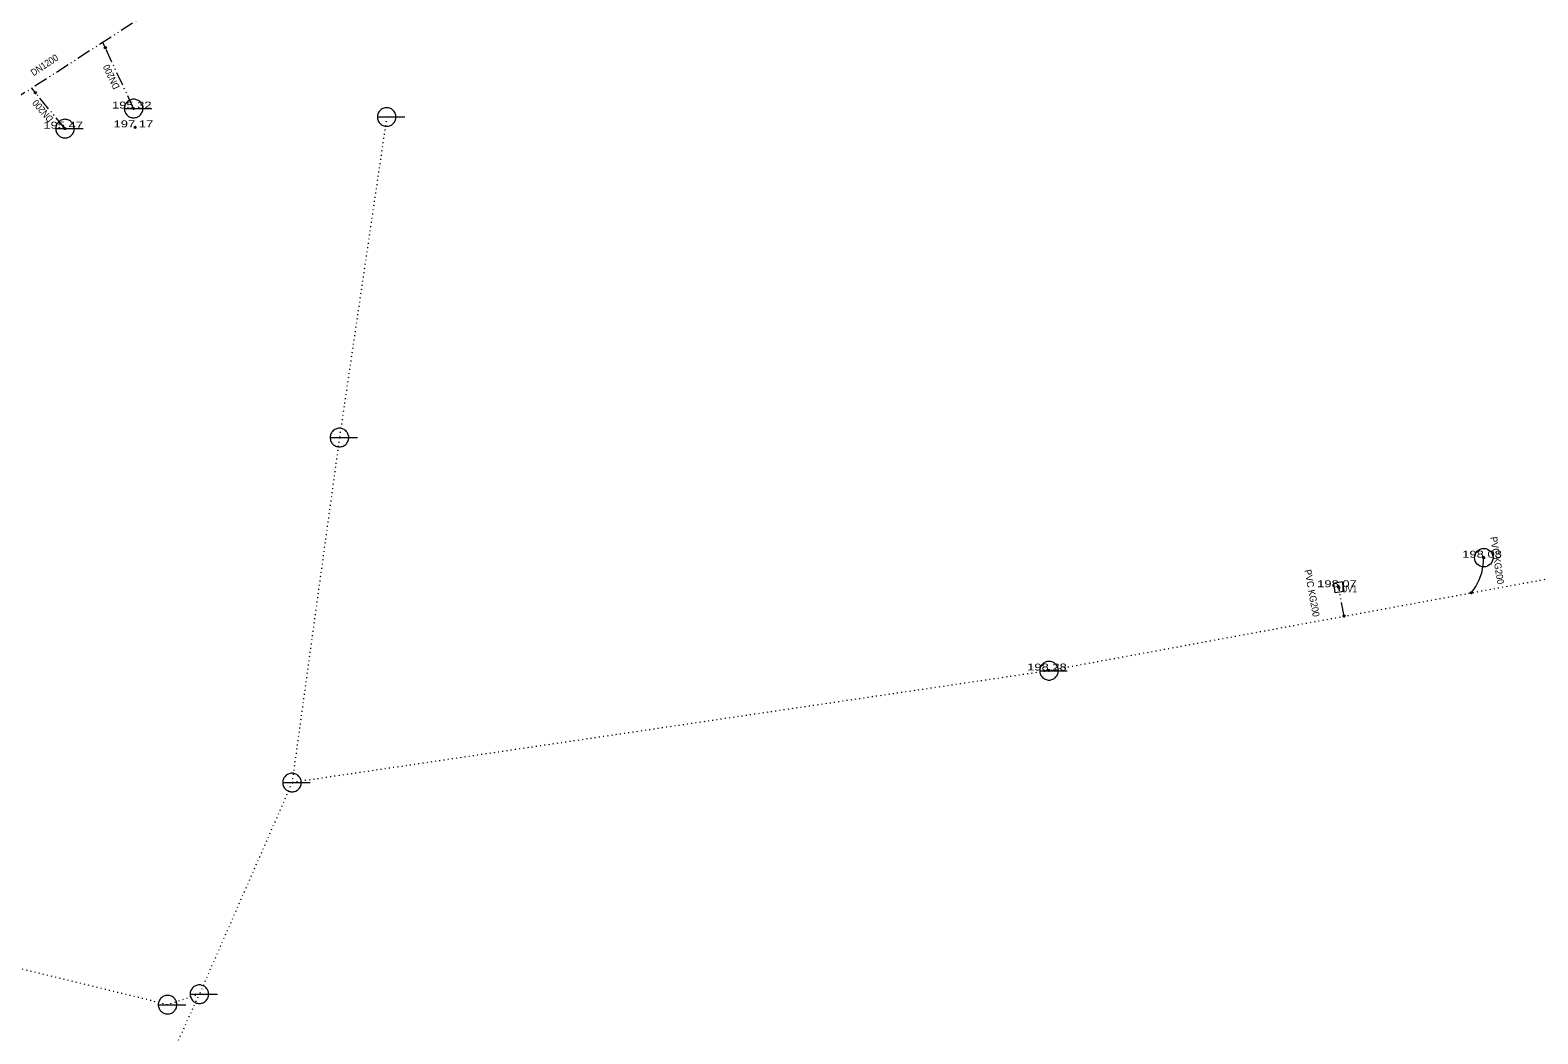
# Model space of a CAD drawing. Extents: x -688177 to -687620, y -1056713 to -1056287.
# Drawn here: x -687948.5 to -687785.1, y -1056606.6 to -1056497.8 of the extents above; entities that cross this region are included whole.
import ezdxf
from ezdxf.enums import TextEntityAlignment as Align

# ---------------------------------------------------------------- set-up
doc = ezdxf.new("R2010")
doc.units = 0
doc.header["$LTSCALE"] = 0.3
doc.header["$PDMODE"] = 32
doc.header["$PDSIZE"] = 0.15
for name, pattern in [('DASH_DOUBLE_DOT', [9.2, 5, -1.2, 0.3, -1.2, 0.3, -1.2]), ('DOTTED', [1.5, 0.3, -1.2]), ('LONG_DASHED', [7.5, 6, -1.5])]:
    doc.linetypes.add(name, pattern=pattern)
for name, color, linetype in [('1', 7, 'Continuous'), ('18', 7, 'Continuous'), ('19', 7, 'Continuous'), ('3', 7, 'Continuous')]:
    doc.layers.add(name, color=color, linetype=linetype)
for name, color, linetype, lineweight in [('10', 7, 'Continuous', 13), ('12', 7, 'Continuous', 13), ('46', 7, 'DOTTED', 13), ('50', 7, 'LONG_DASHED', 13), ('51', 7, 'DASH_DOUBLE_DOT', 13)]:
    doc.layers.add(name, color=color, linetype=linetype, lineweight=lineweight)

msp = doc.modelspace()

# ---------------------------------------------------------------- linework, layer by layer
at = {"layer": '1'}
for p in [(-687940.32, -1056499.71), (-687947.88, -1056504.6), (-687937.24, -1056506.31), (-687944.68, -1056508.49), (-687937.07, -1056508.35), (-687790.91, -1056555), (-687806.63, -1056558.2), (-687792.25, -1056558.81), (-687806.05, -1056561.34), (-687838.06, -1056567.23)]:
    msp.add_point(p, dxfattribs=at)
at = {"layer": '10'}
msp.add_line((-687806.669, -1056557.953), (-687806.591, -1056558.447), dxfattribs=at)
msp.add_lwpolyline([(-687807.202, -1056557.784), (-687807.046, -1056558.772), (-687806.058, -1056558.616), (-687806.214, -1056557.628)], close=True, dxfattribs=at)
msp.add_circle((-687790.91, -1056555), 1, dxfattribs=at)
at = {"layer": '12'}
for p, q in [((-687938.248, -1056506.31), (-687935.272, -1056506.31)), ((-687910.818, -1056507.23), (-687907.842, -1056507.23)), ((-687945.688, -1056508.49), (-687942.712, -1056508.49)), ((-687915.938, -1056541.98), (-687912.962, -1056541.98)), ((-687839.038, -1056567.26), (-687836.062, -1056567.26)), ((-687921.078, -1056579.38), (-687918.102, -1056579.38)), ((-687931.118, -1056602.32), (-687928.142, -1056602.32)), ((-687934.568, -1056603.46), (-687931.592, -1056603.46))]:
    msp.add_line(p, q, dxfattribs=at)
for points in [[(-687937.24, -1056505.302), (-687937.345, -1056505.308), (-687937.449, -1056505.324), (-687937.551, -1056505.352), (-687937.65, -1056505.39), (-687937.744, -1056505.437), (-687937.832, -1056505.495), (-687937.914, -1056505.561), (-687937.989, -1056505.636), (-687938.055, -1056505.718), (-687938.113, -1056505.806), (-687938.16, -1056505.9), (-687938.198, -1056505.999), (-687938.226, -1056506.101), (-687938.242, -1056506.205), (-687938.248, -1056506.31), (-687938.242, -1056506.415), (-687938.226, -1056506.52), (-687938.198, -1056506.622), (-687938.16, -1056506.72), (-687938.113, -1056506.814), (-687938.055, -1056506.903), (-687937.989, -1056506.985), (-687937.914, -1056507.059), (-687937.832, -1056507.125), (-687937.744, -1056507.183), (-687937.65, -1056507.231), (-687937.551, -1056507.269), (-687937.449, -1056507.296), (-687937.345, -1056507.312), (-687937.24, -1056507.318), (-687937.135, -1056507.312), (-687937.03, -1056507.296), (-687936.928, -1056507.269), (-687936.83, -1056507.231), (-687936.736, -1056507.183), (-687936.647, -1056507.125), (-687936.565, -1056507.059), (-687936.491, -1056506.985), (-687936.425, -1056506.903), (-687936.367, -1056506.814), (-687936.319, -1056506.72), (-687936.281, -1056506.622), (-687936.254, -1056506.52), (-687936.238, -1056506.415), (-687936.232, -1056506.31), (-687936.238, -1056506.205), (-687936.254, -1056506.101), (-687936.281, -1056505.999), (-687936.319, -1056505.9), (-687936.367, -1056505.806), (-687936.425, -1056505.718), (-687936.491, -1056505.636), (-687936.565, -1056505.561), (-687936.647, -1056505.495), (-687936.736, -1056505.437), (-687936.83, -1056505.39), (-687936.928, -1056505.352), (-687937.03, -1056505.324), (-687937.135, -1056505.308)], [(-687909.81, -1056506.222), (-687909.915, -1056506.228), (-687910.019, -1056506.244), (-687910.121, -1056506.272), (-687910.22, -1056506.31), (-687910.314, -1056506.357), (-687910.402, -1056506.415), (-687910.484, -1056506.481), (-687910.559, -1056506.556), (-687910.625, -1056506.638), (-687910.683, -1056506.726), (-687910.73, -1056506.82), (-687910.768, -1056506.919), (-687910.796, -1056507.021), (-687910.812, -1056507.125), (-687910.818, -1056507.23), (-687910.812, -1056507.335), (-687910.796, -1056507.44), (-687910.768, -1056507.542), (-687910.73, -1056507.64), (-687910.683, -1056507.734), (-687910.625, -1056507.823), (-687910.559, -1056507.905), (-687910.484, -1056507.979), (-687910.402, -1056508.045), (-687910.314, -1056508.103), (-687910.22, -1056508.151), (-687910.121, -1056508.189), (-687910.019, -1056508.216), (-687909.915, -1056508.232), (-687909.81, -1056508.238), (-687909.705, -1056508.232), (-687909.6, -1056508.216), (-687909.498, -1056508.189), (-687909.4, -1056508.151), (-687909.306, -1056508.103), (-687909.217, -1056508.045), (-687909.135, -1056507.979), (-687909.061, -1056507.905), (-687908.995, -1056507.823), (-687908.937, -1056507.734), (-687908.889, -1056507.64), (-687908.851, -1056507.542), (-687908.824, -1056507.44), (-687908.808, -1056507.335), (-687908.802, -1056507.23), (-687908.808, -1056507.125), (-687908.824, -1056507.021), (-687908.851, -1056506.919), (-687908.889, -1056506.82), (-687908.937, -1056506.726), (-687908.995, -1056506.638), (-687909.061, -1056506.556), (-687909.135, -1056506.481), (-687909.217, -1056506.415), (-687909.306, -1056506.357), (-687909.4, -1056506.31), (-687909.498, -1056506.272), (-687909.6, -1056506.244), (-687909.705, -1056506.228)], [(-687944.68, -1056507.482), (-687944.785, -1056507.488), (-687944.889, -1056507.504), (-687944.991, -1056507.532), (-687945.09, -1056507.57), (-687945.184, -1056507.617), (-687945.272, -1056507.675), (-687945.354, -1056507.741), (-687945.429, -1056507.816), (-687945.495, -1056507.898), (-687945.553, -1056507.986), (-687945.6, -1056508.08), (-687945.638, -1056508.179), (-687945.666, -1056508.281), (-687945.682, -1056508.385), (-687945.688, -1056508.49), (-687945.682, -1056508.595), (-687945.666, -1056508.7), (-687945.638, -1056508.802), (-687945.6, -1056508.9), (-687945.553, -1056508.994), (-687945.495, -1056509.083), (-687945.429, -1056509.165), (-687945.354, -1056509.239), (-687945.272, -1056509.305), (-687945.184, -1056509.363), (-687945.09, -1056509.411), (-687944.991, -1056509.449), (-687944.889, -1056509.476), (-687944.785, -1056509.492), (-687944.68, -1056509.498), (-687944.575, -1056509.492), (-687944.47, -1056509.476), (-687944.368, -1056509.449), (-687944.27, -1056509.411), (-687944.176, -1056509.363), (-687944.087, -1056509.305), (-687944.005, -1056509.239), (-687943.931, -1056509.165), (-687943.865, -1056509.083), (-687943.807, -1056508.994), (-687943.759, -1056508.9), (-687943.721, -1056508.802), (-687943.694, -1056508.7), (-687943.678, -1056508.595), (-687943.672, -1056508.49), (-687943.678, -1056508.385), (-687943.694, -1056508.281), (-687943.721, -1056508.179), (-687943.759, -1056508.08), (-687943.807, -1056507.986), (-687943.865, -1056507.898), (-687943.931, -1056507.816), (-687944.005, -1056507.741), (-687944.087, -1056507.675), (-687944.176, -1056507.617), (-687944.27, -1056507.57), (-687944.368, -1056507.532), (-687944.47, -1056507.504), (-687944.575, -1056507.488)], [(-687914.93, -1056540.972), (-687915.035, -1056540.978), (-687915.139, -1056540.994), (-687915.241, -1056541.022), (-687915.34, -1056541.06), (-687915.434, -1056541.107), (-687915.522, -1056541.165), (-687915.604, -1056541.231), (-687915.679, -1056541.306), (-687915.745, -1056541.388), (-687915.803, -1056541.476), (-687915.85, -1056541.57), (-687915.888, -1056541.669), (-687915.916, -1056541.771), (-687915.932, -1056541.875), (-687915.938, -1056541.98), (-687915.932, -1056542.085), (-687915.916, -1056542.19), (-687915.888, -1056542.292), (-687915.85, -1056542.39), (-687915.803, -1056542.484), (-687915.745, -1056542.573), (-687915.679, -1056542.655), (-687915.604, -1056542.729), (-687915.522, -1056542.795), (-687915.434, -1056542.853), (-687915.34, -1056542.901), (-687915.241, -1056542.939), (-687915.139, -1056542.966), (-687915.035, -1056542.982), (-687914.93, -1056542.988), (-687914.825, -1056542.982), (-687914.72, -1056542.966), (-687914.618, -1056542.939), (-687914.52, -1056542.901), (-687914.426, -1056542.853), (-687914.337, -1056542.795), (-687914.255, -1056542.729), (-687914.181, -1056542.655), (-687914.115, -1056542.573), (-687914.057, -1056542.484), (-687914.009, -1056542.39), (-687913.971, -1056542.292), (-687913.944, -1056542.19), (-687913.928, -1056542.085), (-687913.922, -1056541.98), (-687913.928, -1056541.875), (-687913.944, -1056541.771), (-687913.971, -1056541.669), (-687914.009, -1056541.57), (-687914.057, -1056541.476), (-687914.115, -1056541.388), (-687914.181, -1056541.306), (-687914.255, -1056541.231), (-687914.337, -1056541.165), (-687914.426, -1056541.107), (-687914.52, -1056541.06), (-687914.618, -1056541.022), (-687914.72, -1056540.994), (-687914.825, -1056540.978)], [(-687838.03, -1056566.252), (-687838.135, -1056566.258), (-687838.239, -1056566.274), (-687838.341, -1056566.302), (-687838.44, -1056566.34), (-687838.534, -1056566.387), (-687838.622, -1056566.445), (-687838.704, -1056566.511), (-687838.779, -1056566.586), (-687838.845, -1056566.668), (-687838.903, -1056566.756), (-687838.95, -1056566.85), (-687838.988, -1056566.949), (-687839.016, -1056567.051), (-687839.032, -1056567.155), (-687839.038, -1056567.26), (-687839.032, -1056567.365), (-687839.016, -1056567.47), (-687838.988, -1056567.572), (-687838.95, -1056567.67), (-687838.903, -1056567.764), (-687838.845, -1056567.853), (-687838.779, -1056567.935), (-687838.704, -1056568.009), (-687838.622, -1056568.075), (-687838.534, -1056568.133), (-687838.44, -1056568.181), (-687838.341, -1056568.219), (-687838.239, -1056568.246), (-687838.135, -1056568.262), (-687838.03, -1056568.268), (-687837.925, -1056568.262), (-687837.82, -1056568.246), (-687837.718, -1056568.219), (-687837.62, -1056568.181), (-687837.526, -1056568.133), (-687837.437, -1056568.075), (-687837.355, -1056568.009), (-687837.281, -1056567.935), (-687837.215, -1056567.853), (-687837.157, -1056567.764), (-687837.109, -1056567.67), (-687837.071, -1056567.572), (-687837.044, -1056567.47), (-687837.028, -1056567.365), (-687837.022, -1056567.26), (-687837.028, -1056567.155), (-687837.044, -1056567.051), (-687837.071, -1056566.949), (-687837.109, -1056566.85), (-687837.157, -1056566.756), (-687837.215, -1056566.668), (-687837.281, -1056566.586), (-687837.355, -1056566.511), (-687837.437, -1056566.445), (-687837.526, -1056566.387), (-687837.62, -1056566.34), (-687837.718, -1056566.302), (-687837.82, -1056566.274), (-687837.925, -1056566.258)], [(-687920.07, -1056578.372), (-687920.175, -1056578.378), (-687920.279, -1056578.394), (-687920.381, -1056578.422), (-687920.48, -1056578.46), (-687920.574, -1056578.507), (-687920.662, -1056578.565), (-687920.744, -1056578.631), (-687920.819, -1056578.706), (-687920.885, -1056578.788), (-687920.943, -1056578.876), (-687920.99, -1056578.97), (-687921.028, -1056579.069), (-687921.056, -1056579.171), (-687921.072, -1056579.275), (-687921.078, -1056579.38), (-687921.072, -1056579.485), (-687921.056, -1056579.59), (-687921.028, -1056579.692), (-687920.99, -1056579.79), (-687920.943, -1056579.884), (-687920.885, -1056579.973), (-687920.819, -1056580.055), (-687920.744, -1056580.129), (-687920.662, -1056580.195), (-687920.574, -1056580.253), (-687920.48, -1056580.301), (-687920.381, -1056580.339), (-687920.279, -1056580.366), (-687920.175, -1056580.382), (-687920.07, -1056580.388), (-687919.965, -1056580.382), (-687919.86, -1056580.366), (-687919.758, -1056580.339), (-687919.66, -1056580.301), (-687919.566, -1056580.253), (-687919.477, -1056580.195), (-687919.395, -1056580.129), (-687919.321, -1056580.055), (-687919.255, -1056579.973), (-687919.197, -1056579.884), (-687919.149, -1056579.79), (-687919.111, -1056579.692), (-687919.084, -1056579.59), (-687919.068, -1056579.485), (-687919.062, -1056579.38), (-687919.068, -1056579.275), (-687919.084, -1056579.171), (-687919.111, -1056579.069), (-687919.149, -1056578.97), (-687919.197, -1056578.876), (-687919.255, -1056578.788), (-687919.321, -1056578.706), (-687919.395, -1056578.631), (-687919.477, -1056578.565), (-687919.566, -1056578.507), (-687919.66, -1056578.46), (-687919.758, -1056578.422), (-687919.86, -1056578.394), (-687919.965, -1056578.378)], [(-687930.11, -1056601.312), (-687930.215, -1056601.318), (-687930.319, -1056601.334), (-687930.421, -1056601.362), (-687930.52, -1056601.4), (-687930.614, -1056601.447), (-687930.702, -1056601.505), (-687930.784, -1056601.571), (-687930.859, -1056601.646), (-687930.925, -1056601.728), (-687930.983, -1056601.816), (-687931.03, -1056601.91), (-687931.068, -1056602.009), (-687931.096, -1056602.111), (-687931.112, -1056602.215), (-687931.118, -1056602.32), (-687931.112, -1056602.425), (-687931.096, -1056602.53), (-687931.068, -1056602.632), (-687931.03, -1056602.73), (-687930.983, -1056602.824), (-687930.925, -1056602.913), (-687930.859, -1056602.995), (-687930.784, -1056603.069), (-687930.702, -1056603.135), (-687930.614, -1056603.193), (-687930.52, -1056603.241), (-687930.421, -1056603.279), (-687930.319, -1056603.306), (-687930.215, -1056603.322), (-687930.11, -1056603.328), (-687930.005, -1056603.322), (-687929.9, -1056603.306), (-687929.798, -1056603.279), (-687929.7, -1056603.241), (-687929.606, -1056603.193), (-687929.517, -1056603.135), (-687929.435, -1056603.069), (-687929.361, -1056602.995), (-687929.295, -1056602.913), (-687929.237, -1056602.824), (-687929.189, -1056602.73), (-687929.151, -1056602.632), (-687929.124, -1056602.53), (-687929.108, -1056602.425), (-687929.102, -1056602.32), (-687929.108, -1056602.215), (-687929.124, -1056602.111), (-687929.151, -1056602.009), (-687929.189, -1056601.91), (-687929.237, -1056601.816), (-687929.295, -1056601.728), (-687929.361, -1056601.646), (-687929.435, -1056601.571), (-687929.517, -1056601.505), (-687929.606, -1056601.447), (-687929.7, -1056601.4), (-687929.798, -1056601.362), (-687929.9, -1056601.334), (-687930.005, -1056601.318)], [(-687933.56, -1056602.452), (-687933.665, -1056602.458), (-687933.769, -1056602.474), (-687933.871, -1056602.502), (-687933.97, -1056602.54), (-687934.064, -1056602.587), (-687934.152, -1056602.645), (-687934.234, -1056602.711), (-687934.309, -1056602.786), (-687934.375, -1056602.868), (-687934.433, -1056602.956), (-687934.48, -1056603.05), (-687934.518, -1056603.149), (-687934.546, -1056603.251), (-687934.562, -1056603.355), (-687934.568, -1056603.46), (-687934.562, -1056603.565), (-687934.546, -1056603.67), (-687934.518, -1056603.772), (-687934.48, -1056603.87), (-687934.433, -1056603.964), (-687934.375, -1056604.053), (-687934.309, -1056604.135), (-687934.234, -1056604.209), (-687934.152, -1056604.275), (-687934.064, -1056604.333), (-687933.97, -1056604.381), (-687933.871, -1056604.419), (-687933.769, -1056604.446), (-687933.665, -1056604.462), (-687933.56, -1056604.468), (-687933.455, -1056604.462), (-687933.35, -1056604.446), (-687933.248, -1056604.419), (-687933.15, -1056604.381), (-687933.056, -1056604.333), (-687932.967, -1056604.275), (-687932.885, -1056604.209), (-687932.811, -1056604.135), (-687932.745, -1056604.053), (-687932.687, -1056603.964), (-687932.639, -1056603.87), (-687932.601, -1056603.772), (-687932.574, -1056603.67), (-687932.558, -1056603.565), (-687932.552, -1056603.46), (-687932.558, -1056603.355), (-687932.574, -1056603.251), (-687932.601, -1056603.149), (-687932.639, -1056603.05), (-687932.687, -1056602.956), (-687932.745, -1056602.868), (-687932.811, -1056602.786), (-687932.885, -1056602.711), (-687932.967, -1056602.645), (-687933.056, -1056602.587), (-687933.15, -1056602.54), (-687933.248, -1056602.502), (-687933.35, -1056602.474), (-687933.455, -1056602.458)]]:
    msp.add_lwpolyline(points, close=True, dxfattribs=at)
at = {"layer": '46'}
msp.add_line((-687838.03, -1056567.26), (-687920.07, -1056579.38), dxfattribs=at)
at = {"layer": '46', "linetype": 'DASH_DOUBLE_DOT'}
msp.add_lwpolyline([(-687931.68, -1056493.1), (-687932.67, -1056494.04), (-687962.33, -1056513.18), (-687963.07, -1056513.7)], dxfattribs=at)
at = {"layer": '46'}
for points in [[(-687909.81, -1056507.23), (-687914.93, -1056541.98), (-687920.07, -1056579.39), (-687930.11, -1056602.32)], [(-687678.6, -1056529.05), (-687744.5, -1056550.06), (-687838.03, -1056567.26)], [(-687930.11, -1056602.32), (-687933.56, -1056603.46), (-688001.96, -1056586.72)], [(-687891.76, -1056663.71), (-687915.23, -1056649.1), (-687939.41, -1056622.82), (-687930.11, -1056602.32)]]:
    msp.add_lwpolyline(points, dxfattribs=at)
at = {"layer": '50', "linetype": 'DASH_DOUBLE_DOT'}
msp.add_line((-687806.052, -1056561.344), (-687806.63, -1056558.2), dxfattribs=at)
msp.add_lwpolyline([(-687792.25, -1056558.81), (-687791.778, -1056558.136), (-687791.402, -1056557.404), (-687791.129, -1056556.627), (-687790.964, -1056555.821), (-687790.91, -1056555)], dxfattribs=at)
at = {"layer": '51'}
for points in [[(-687937.24, -1056506.31), (-687940.32, -1056499.71), (-687940.58, -1056499.15)], [(-687944.68, -1056508.49), (-687947.88, -1056504.6), (-687948.28, -1056504.12)]]:
    msp.add_lwpolyline(points, dxfattribs=at)

# ---------------------------------------------------------------- texts
at = {"layer": '18', "width": 0.9}
msp.add_text('DN1200', height=0.75, rotation=33.518, dxfattribs=at).set_placement((-687948.078, -1056502.825))
at = {"layer": '19'}
for s, rotation, width, p in [('DN200', 115.222, 0.9, (-687938.719, -1056503.992)), ('DN200', 130.749, 0.9, (-687945.891, -1056507.393)), ('PVC KG200', 278.595, 0.95, (-687790.219, -1056552.783)), ('PVC KG200', 280.42, 0.95, (-687810.364, -1056556.359))]:
    msp.add_text(s, height=0.75, rotation=rotation, dxfattribs=dict(at, width=width)).set_placement(p)
at = {"layer": '19', "width": 0.85}
msp.add_text('UV1', height=0.75, dxfattribs=at).set_placement((-687806.32, -1056558.76))
at = {"layer": '3', "width": 1.4}
for s, p in [('195 32 ', (-687937.24, -1056506.31)), ('195 47 ', (-687944.68, -1056508.49)), ('197 17 ', (-687937.07, -1056508.35)), ('198 08 ', (-687790.91, -1056555)), ('198 07 ', (-687806.63, -1056558.2)), ('198 28 ', (-687838.06, -1056567.23))]:
    msp.add_text(s, height=0.75, dxfattribs=at).set_placement(p, align=Align.CENTER)

doc.saveas('drawing.dxf')
